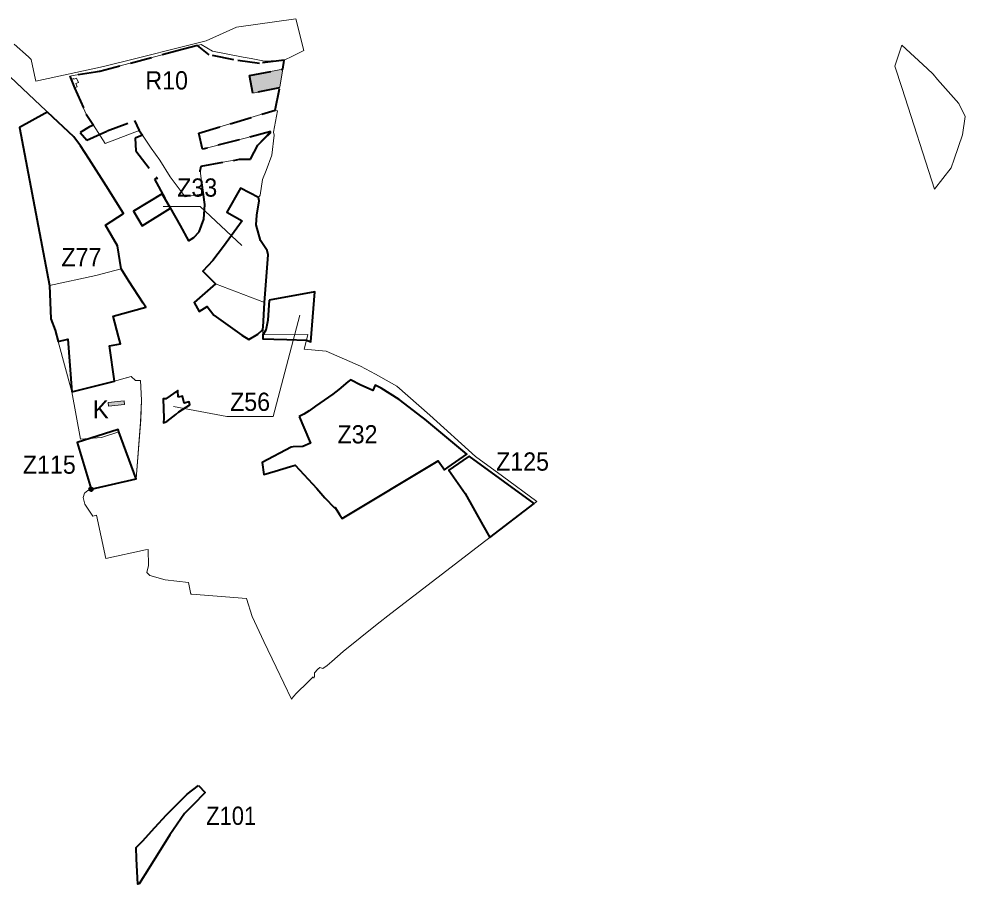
# Model space of a CAD drawing. Extents: x -650276 to -642489, y -1074425 to -1066658.
# Drawn here: x -645214 to -643970, y -1073665 to -1072527 of the extents above; entities that cross this region are included whole.
import ezdxf

# ---------------------------------------------------------------- set-up
doc = ezdxf.new("R2010")
doc.units = 0
doc.header["$LTSCALE"] = 9.6
doc.header["$PDMODE"] = 32
doc.header["$PDSIZE"] = 4.8
doc.linetypes.add('MEDIUM_DASHED', pattern=[4.5, 3, -1.5])
for name, color, linetype, lineweight in [('1', 7, 'Continuous', 13), ('42', 7, 'Continuous', 25), ('43', 7, 'Continuous', 13), ('44', 7, 'Continuous', 40), ('45', 7, 'Continuous', 40), ('46', 7, 'Continuous', 13), ('47', 7, 'Continuous', 13), ('61', 7, 'MEDIUM_DASHED', 40), ('62', 7, 'Continuous', 35)]:
    doc.layers.add(name, color=color, linetype=linetype, lineweight=lineweight)

msp = doc.modelspace()

# ---------------------------------------------------------------- hatches: boundary and pattern name
at = {"layer": '1'}
for points in [[(-644867.36, -1072593.58), (-644871.3, -1072616.78), (-644871.55, -1072618.07), (-644872.93, -1072618.35), (-644906.5, -1072625.07), (-644906.56, -1072624.79), (-644910.44, -1072605.5), (-644911.21, -1072601.67)], [(-645075.24, -1073034.31), (-645075.78, -1073029.28), (-645096.64, -1073031.51), (-645096.19, -1073036.55)]]:
    msp.add_hatch(color=256, dxfattribs=at).paths.add_polyline_path(points)

# ---------------------------------------------------------------- linework, layer by layer
for p, q in [((-645137.62, -1072616.42), (-645139.37, -1072612.36)), ((-645121.96, -1072711.68), (-645076.66, -1072783.06))]:
    msp.add_line(p, q, dxfattribs=at)
for points in [[(-645051.87, -1072680.22), (-645056.08, -1072674.07), (-645100.9, -1072691.31), (-645116.1, -1072667.08), (-645125.58, -1072652.42), (-645140.96, -1072617.82), (-645145.52, -1072606.48), (-645147.13, -1072602.79), (-645101.56, -1072594.21), (-645042.549, -1072578.848), (-644997.92, -1072567.23), (-644974.74, -1072561.19), (-644959.46, -1072569.74), (-644919.23, -1072577.46), (-644908.59, -1072579.51), (-644891.4, -1072582.77), (-644865.31, -1072581.58), (-644854.54, -1072576.36), (-644839.78, -1072569.03), (-644850.1, -1072527.37), (-644928.23, -1072538), (-644967.97, -1072556.17), (-644999.72, -1072564.24), (-645058.484, -1072578.787), (-645102.73, -1072589.74), (-645192.06, -1072609.19), (-645193.675, -1072601.359), (-645197.97, -1072580.53), (-645201.69, -1072577.19), (-645220.27, -1072560.51)], [(-645242, -1072588.6), (-645185.95, -1072641.32), (-645142.1, -1072682.57), (-645133.26, -1072694.17), (-645121.96, -1072711.68)], [(-645142.16, -1072605.87), (-645145.23, -1072607.15), (-645141.72, -1072615.2), (-645140.96, -1072617.82), (-645137.62, -1072616.42)], [(-645139.37, -1072612.36), (-645135.94, -1072611.02), (-645138.46, -1072605.08), (-645141.92, -1072606.43), (-645142.16, -1072605.87)], [(-645144.37, -1073017.64), (-645088.62, -1073003.45), (-645073.23, -1072999.05), (-645066.66, -1072997.3), (-645060.95, -1073002.68), (-645054.44, -1073002.54), (-645052.94, -1073028.58), (-645053.83, -1073054.04), (-645060.1, -1073131.68), (-645119.34, -1073145.61), (-645123.616, -1073147.195), (-645127.781, -1073150.527), (-645129.447, -1073156.525), (-645127.615, -1073165.356), (-645116.951, -1073180.851), (-645111.98, -1073179.822), (-645099.78, -1073236.52), (-645047.59, -1073225.3), (-645044.246, -1073224.619), (-645043.68, -1073245.61), (-645045.79, -1073255.05), (-645042.08, -1073258.81), (-645022.07, -1073264.52), (-644991.26, -1073268.06), (-644988.14, -1073283.32), (-644986.64, -1073283.44), (-644914.85, -1073289.05), (-644907.47, -1073312.85), (-644891.94, -1073345.72), (-644876.05, -1073379.3), (-644855.81, -1073421.57), (-644852.94, -1073418.04), (-644849.42, -1073413.72), (-644834.38, -1073399.18), (-644827.25, -1073392.29), (-644826.58, -1073394.05), (-644825.33, -1073391.59), (-644825.58, -1073386.93), (-644820.95, -1073381.95), (-644818.67, -1073379.69), (-644814.49, -1073381.06), (-644808.69, -1073377.3), (-644802.84, -1073372.09), (-644787.75, -1073358.68), (-644743.23, -1073322.94), (-644725.21, -1073308.93), (-644664.58, -1073262.31), (-644600.46, -1073213), (-644595.18, -1073208.98), (-644536.62, -1073164.33), (-644533.07, -1073161.68), (-644578.557, -1073128.324), (-644613.7, -1073102.55), (-644674.06, -1073048.04), (-644717.12, -1073009.9), (-644745.2, -1072994.46), (-644764.92, -1072983.61), (-644810.21, -1072963.95), (-644839, -1072961.28), (-644835.99, -1072949.74), (-644834.41, -1072942.14), (-644893.37, -1072942.61), (-644892.86, -1072932.6), (-644891.2, -1072900.09), (-644955.49, -1072875.78), (-644969.93, -1072861.43), (-644972.28, -1072859.02), (-644959.24, -1072844.92), (-644945.2, -1072826.3), (-644920.46, -1072792.92), (-644940.8, -1072781.48), (-644922.88, -1072749.97), (-644899.2, -1072762.14), (-644897.07, -1072759.05), (-644893.7, -1072738.41), (-644889.26, -1072726.4), (-644881.82, -1072706.26), (-644878.69, -1072680.27), (-644879.59, -1072676.3), (-644874.136, -1072647.984), (-644877.32, -1072647.4), (-644977.57, -1072677.66), (-644972.68, -1072698.65), (-644882.85, -1072675.56), (-644883.17, -1072677.19), (-644899.86, -1072693.27), (-644909.76, -1072711.64), (-644924.08, -1072711.8), (-644974.61, -1072720.9), (-644975.88, -1072727.2), (-644971.9, -1072757.34), (-644995.61, -1072761.19), (-645015.21, -1072734.72), (-645029.08, -1072713.14), (-645040.29, -1072697.03), (-645051.87, -1072680.22)], [(-645076.66, -1072783.06), (-645100.27, -1072798.46), (-645084.47, -1072825.67), (-645079.81, -1072855.89), (-645112.94, -1072864.45)], [(-645112.94, -1072864.45), (-645174.13, -1072877.93), (-645172.28, -1072921.42), (-645166.48, -1072936.5), (-645162.38, -1072951.55), (-645144.37, -1073017.64)]]:
    msp.add_lwpolyline(points, dxfattribs=at)
for points in [[(-644010.26, -1072751.03), (-643988.48, -1072723.23), (-643984.55, -1072711.81), (-643973.49, -1072679.63), (-643970.28, -1072655.79), (-643978.55, -1072638.72), (-644006.41, -1072606.81), (-644012.35, -1072600), (-644020.16, -1072592.7), (-644053.21, -1072561.84), (-644062.69, -1072589.53), (-644053.2, -1072618.77)], [(-644867.36, -1072593.58), (-644871.3, -1072616.78), (-644871.55, -1072618.07), (-644872.93, -1072618.35), (-644906.5, -1072625.07), (-644906.56, -1072624.79), (-644910.44, -1072605.5), (-644911.21, -1072601.67)], [(-645075.24, -1073034.31), (-645075.78, -1073029.28), (-645096.64, -1073031.51), (-645096.19, -1073036.55)]]:
    msp.add_lwpolyline(points, close=True, dxfattribs=at)
at = {"layer": '42'}
msp.add_lwpolyline([(-644845.72, -1073050.14), (-644839.57, -1073064.5), (-644830.81, -1073084.98), (-644840.89, -1073089.3), (-644853.8, -1073089.99), (-644856.4, -1073090.13), (-644894.15, -1073110.3), (-644892.14, -1073126.36), (-644877.32, -1073121.83), (-644856.97, -1073115.6), (-644851, -1073113.77), (-644822.62, -1073144.71), (-644811.96, -1073156.75), (-644799.26, -1073170.13), (-644798.38, -1073169.56), (-644792.59, -1073178.73), (-644789.31, -1073183.93), (-644663.17, -1073108.27), (-644656.56, -1073117.4), (-644654.61, -1073120.1), (-644649.7, -1073116.65), (-644625.26, -1073099.51), (-644680.69, -1073053.67), (-644684.09, -1073050.8), (-644714.42, -1073027.62), (-644714.42, -1073027.62), (-644737.88, -1073012.62), (-644745.73, -1073008.64), (-644748.95, -1073015.64), (-644757.73, -1073012.05), (-644764.69, -1073008.87), (-644778.38, -1073001.84), (-644781.52, -1073004.39), (-644793.743, -1073014.293), (-644801.54, -1073020.61), (-644824.08, -1073036.56), (-644832.7, -1073042.34), (-644839.47, -1073046.89)], close=True, dxfattribs=at)
at = {"layer": '44'}
msp.add_lwpolyline([(-644977.924, -1073535.072), (-644969.117, -1073544.254), (-644985.66, -1073560.69), (-644996.41, -1073571.97), (-645001.267, -1073578.582), (-645015.55, -1073599.96), (-645043.35, -1073644.04), (-645056.06, -1073664.2), (-645057.87, -1073664.55), (-645059.35, -1073631.3), (-645060.009, -1073616.53), (-645051.513, -1073608.124), (-645035.303, -1073590.199), (-645020.11, -1073573.585), (-644993.044, -1073546.324)], close=True, dxfattribs=at)
at = {"layer": '45'}
for points in [[(-645144.37, -1073017.64), (-645088.62, -1073003.45), (-645095.04, -1072957.07), (-645080.61, -1072954.43), (-645083.13, -1072944.94), (-645090.34, -1072917.86), (-645047.42, -1072906.05), (-645050.6, -1072901.03), (-645069.55, -1072872.12), (-645071.87, -1072868.45), (-645079.81, -1072855.89), (-645084.47, -1072825.67), (-645100.27, -1072798.46), (-645076.66, -1072783.06), (-645099.58, -1072746.945), (-645121.96, -1072711.68), (-645133.26, -1072694.17), (-645142.1, -1072682.57), (-645176.757, -1072649.968), (-645180.05, -1072651.77), (-645213.34, -1072669.98), (-645174.13, -1072877.93), (-645172.28, -1072921.42), (-645166.48, -1072936.5), (-645162.379, -1072951.55), (-645149.84, -1072948.13)], [(-645025.61, -1072757.17), (-645063.6, -1072780.26), (-645051.94, -1072799.21), (-645015.02, -1072776.01)], [(-645025.61, -1072757.17), (-645063.6, -1072780.26), (-645051.94, -1072799.21), (-645015.02, -1072776.01)], [(-644884.94, -1072897.19), (-644886.98, -1072923.48), (-644889.65, -1072936.67), (-644893.37, -1072942.61), (-644893.59, -1072947.97), (-644878.86, -1072948.42), (-644861.93, -1072948.94), (-644835.99, -1072949.74), (-644830.25, -1072951.9), (-644825.25, -1072885.96)], [(-644884.94, -1072897.19), (-644886.98, -1072923.48), (-644889.65, -1072936.67), (-644893.37, -1072942.61), (-644893.59, -1072947.97), (-644878.86, -1072948.42), (-644861.93, -1072948.94), (-644835.99, -1072949.74), (-644830.25, -1072951.9), (-644825.25, -1072885.96)], [(-644845.72, -1073050.14), (-644839.57, -1073064.5), (-644830.81, -1073084.98), (-644840.89, -1073089.3), (-644853.8, -1073089.99), (-644856.4, -1073090.13), (-644894.15, -1073110.3), (-644892.14, -1073126.36), (-644877.32, -1073121.83), (-644856.97, -1073115.6), (-644851, -1073113.77), (-644822.62, -1073144.71), (-644811.96, -1073156.75), (-644799.26, -1073170.13), (-644798.38, -1073169.56), (-644792.59, -1073178.73), (-644789.31, -1073183.93), (-644663.17, -1073108.27), (-644656.56, -1073117.4), (-644654.61, -1073120.1), (-644649.7, -1073116.65), (-644625.26, -1073099.51), (-644680.69, -1073053.67), (-644684.09, -1073050.8), (-644714.42, -1073027.62), (-644714.42, -1073027.62), (-644737.88, -1073012.62), (-644745.73, -1073008.64), (-644748.95, -1073015.64), (-644757.73, -1073012.05), (-644764.69, -1073008.87), (-644778.38, -1073001.84), (-644781.52, -1073004.39), (-644793.743, -1073014.293), (-644801.54, -1073020.61), (-644824.08, -1073036.56), (-644832.7, -1073042.34), (-644839.47, -1073046.89)], [(-644845.72, -1073050.14), (-644839.57, -1073064.5), (-644830.81, -1073084.98), (-644840.89, -1073089.3), (-644853.8, -1073089.99), (-644856.4, -1073090.13), (-644894.15, -1073110.3), (-644892.14, -1073126.36), (-644877.32, -1073121.83), (-644856.97, -1073115.6), (-644851, -1073113.77), (-644822.62, -1073144.71), (-644811.96, -1073156.75), (-644799.26, -1073170.13), (-644798.38, -1073169.56), (-644792.59, -1073178.73), (-644789.31, -1073183.93), (-644663.17, -1073108.27), (-644656.56, -1073117.4), (-644654.61, -1073120.1), (-644649.7, -1073116.65), (-644625.26, -1073099.51), (-644680.69, -1073053.67), (-644684.09, -1073050.8), (-644714.42, -1073027.62), (-644714.42, -1073027.62), (-644737.88, -1073012.62), (-644745.73, -1073008.64), (-644748.95, -1073015.64), (-644757.73, -1073012.05), (-644764.69, -1073008.87), (-644778.38, -1073001.84), (-644781.52, -1073004.39), (-644793.743, -1073014.293), (-644801.54, -1073020.61), (-644824.08, -1073036.56), (-644832.7, -1073042.34), (-644839.47, -1073046.89)], [(-645004.82, -1073024.63), (-645005.31, -1073015.68), (-645021.1, -1073026.69), (-645024.71, -1073026.95), (-645023.6, -1073052.12), (-645023.88, -1073058.37), (-645019.57, -1073056.46), (-645007.99, -1073047.31), (-645003.78, -1073043.96), (-644989.34, -1073034.58), (-644990.25, -1073030.54), (-644997.09, -1073032.21), (-644999.23, -1073023.29)], [(-645004.82, -1073024.63), (-645005.31, -1073015.68), (-645021.1, -1073026.69), (-645024.71, -1073026.95), (-645023.6, -1073052.12), (-645023.88, -1073058.37), (-645019.57, -1073056.46), (-645007.99, -1073047.31), (-645003.78, -1073043.96), (-644989.34, -1073034.58), (-644990.25, -1073030.54), (-644997.09, -1073032.21), (-644999.23, -1073023.29)], [(-645119.34, -1073145.61), (-645060.1, -1073131.68), (-645082.6, -1073069.93), (-645083.681, -1073066.962), (-645137.5, -1073083.97)]]:
    msp.add_lwpolyline(points, close=True, dxfattribs=at)
for points in [[(-644902.18, -1072797.88), (-644901.35, -1072785.36), (-644898.29, -1072766.55), (-644899.2, -1072762.14), (-644922.88, -1072749.97), (-644940.8, -1072781.48), (-644920.46, -1072792.92)], [(-644902.18, -1072797.88), (-644901.35, -1072785.36), (-644898.29, -1072766.55), (-644899.2, -1072762.14), (-644922.88, -1072749.97), (-644940.8, -1072781.48), (-644920.46, -1072792.92)], [(-644920.46, -1072792.92), (-644945.2, -1072826.3), (-644959.24, -1072844.92), (-644972.28, -1072859.02), (-644969.93, -1072861.43), (-644955.49, -1072875.78), (-644983.93, -1072900.24), (-644977.16, -1072912.11), (-644966.57, -1072905.23), (-644957.79, -1072916.73), (-644921.18, -1072943.17), (-644911.87, -1072948.76), (-644900.2, -1072941.67), (-644893.77, -1072935.88), (-644892.86, -1072932.6), (-644891.2, -1072900.09), (-644886.61, -1072837.61), (-644887.99, -1072831.83), (-644896.45, -1072818.78), (-644902.18, -1072797.88)], [(-644920.46, -1072792.92), (-644945.2, -1072826.3), (-644959.24, -1072844.92), (-644972.28, -1072859.02), (-644969.93, -1072861.43), (-644955.49, -1072875.78), (-644983.93, -1072900.24), (-644977.16, -1072912.11), (-644966.57, -1072905.23), (-644957.79, -1072916.73), (-644921.18, -1072943.17), (-644911.87, -1072948.76), (-644900.2, -1072941.67), (-644893.77, -1072935.88), (-644892.86, -1072932.6), (-644891.2, -1072900.09), (-644886.61, -1072837.61), (-644887.99, -1072831.83), (-644896.45, -1072818.78), (-644902.18, -1072797.88)], [(-644536.62, -1073164.33), (-644622.03, -1073101.88), (-644630.58, -1073107.78), (-644648.95, -1073120.47), (-644627.53, -1073151.26)], [(-644627.53, -1073151.26), (-644604.13, -1073193), (-644595.18, -1073208.98), (-644536.62, -1073164.33)]]:
    msp.add_lwpolyline(points, dxfattribs=at)
msp.add_point((-645119.34, -1073145.61), dxfattribs=at)
at = {"layer": '46'}
for points in [[(-645024.402, -1072773.758), (-644975.968, -1072773.758), (-644921.076, -1072825.098)], [(-644844.691, -1072916.725), (-644879.683, -1073049.795), (-644940.921, -1073049.795), (-645010.906, -1073036.663)], [(-644844.691, -1072916.725), (-644879.683, -1073049.795), (-644940.921, -1073049.795), (-645010.906, -1073036.663)]]:
    msp.add_lwpolyline(points, dxfattribs=at)
at = {"layer": '47'}
msp.add_line((-645082.6, -1073069.93), (-645060.1, -1073131.68), dxfattribs=at)
for points in [[(-645060.95, -1073002.68), (-645066.66, -1072997.3), (-645066.66, -1072997.3), (-645074.312, -1072999.359), (-645088.62, -1073003.45)], [(-645088.62, -1073003.45), (-645144.37, -1073017.64), (-645133.18, -1073079.73), (-645105.39, -1073077.58), (-645082.6, -1073069.93)], [(-645060.1, -1073131.68), (-645054.12, -1073057.62), (-645052.94, -1073028.58), (-645054.44, -1073002.54), (-645060.95, -1073002.68)]]:
    msp.add_lwpolyline(points, dxfattribs=at)
at = {"layer": '61'}
msp.add_lwpolyline([(-645107.58, -1072596.47), (-645147.13, -1072602.79), (-645140.96, -1072617.82), (-645125.58, -1072652.42), (-645116.1, -1072667.08), (-645121.26, -1072669.32), (-645133.59, -1072676.49), (-645124.933, -1072686.721), (-645098.016, -1072674.425), (-645062.131, -1072660.856), (-645056.08, -1072674.07), (-645051.87, -1072680.22), (-645061.13, -1072683.98), (-645060.48, -1072700.69), (-645032.11, -1072737.28), (-645036.08, -1072737.88), (-645002.34, -1072799.06), (-644991.3, -1072819.12), (-644984.02, -1072814.87), (-644977, -1072807.06), (-644970.87, -1072790.69), (-644969.63, -1072771.21), (-644975.852, -1072727.059), (-644974.61, -1072720.9), (-644924.08, -1072711.8), (-644909.76, -1072711.64), (-644899.86, -1072693.27), (-644882.85, -1072675.56), (-644972.68, -1072698.65), (-644977.57, -1072677.66), (-644877.32, -1072647.4), (-644871.55, -1072618.07), (-644906.56, -1072624.79), (-644911.21, -1072601.67), (-644867.36, -1072593.58), (-644865.31, -1072581.58), (-644897.87, -1072585.78), (-644931.48, -1072581.26), (-644963.97, -1072574.57), (-644979.55, -1072562.44), (-644997.92, -1072567.23)], close=True, dxfattribs=at)

# ---------------------------------------------------------------- texts
at = {"layer": '43'}
msp.add_text('K', height=24, dxfattribs=at).set_placement((-645117.21, -1073052.527))
at = {"layer": '44', "width": 0.9}
msp.add_text('Z101', height=24, dxfattribs=at).set_placement((-644967.996, -1073586.746))
msp.add_text('Z101', height=24, dxfattribs=at).set_placement((-644967.996, -1073586.746))
at = {"layer": '46', "width": 0.95}
for s, p in [('Z33', (-645005.989, -1072761.006)), ('Z77', (-645158.28, -1072852.64)), ('Z56', (-644936.499, -1073042.592)), ('Z56', (-644936.499, -1073042.592)), ('Z32', (-644795.309, -1073085.354)), ('Z32', (-644795.309, -1073085.354)), ('Z125', (-644586.786, -1073121.127)), ('Z115', (-645208.897, -1073125.218))]:
    msp.add_text(s, height=24, dxfattribs=at).set_placement(p)
at = {"layer": '62', "width": 0.95}
msp.add_text('R10', height=24, dxfattribs=at).set_placement((-645047.84, -1072620.116))
msp.add_text('R10', height=24, dxfattribs=at).set_placement((-645047.84, -1072620.116))

doc.saveas('drawing.dxf')
